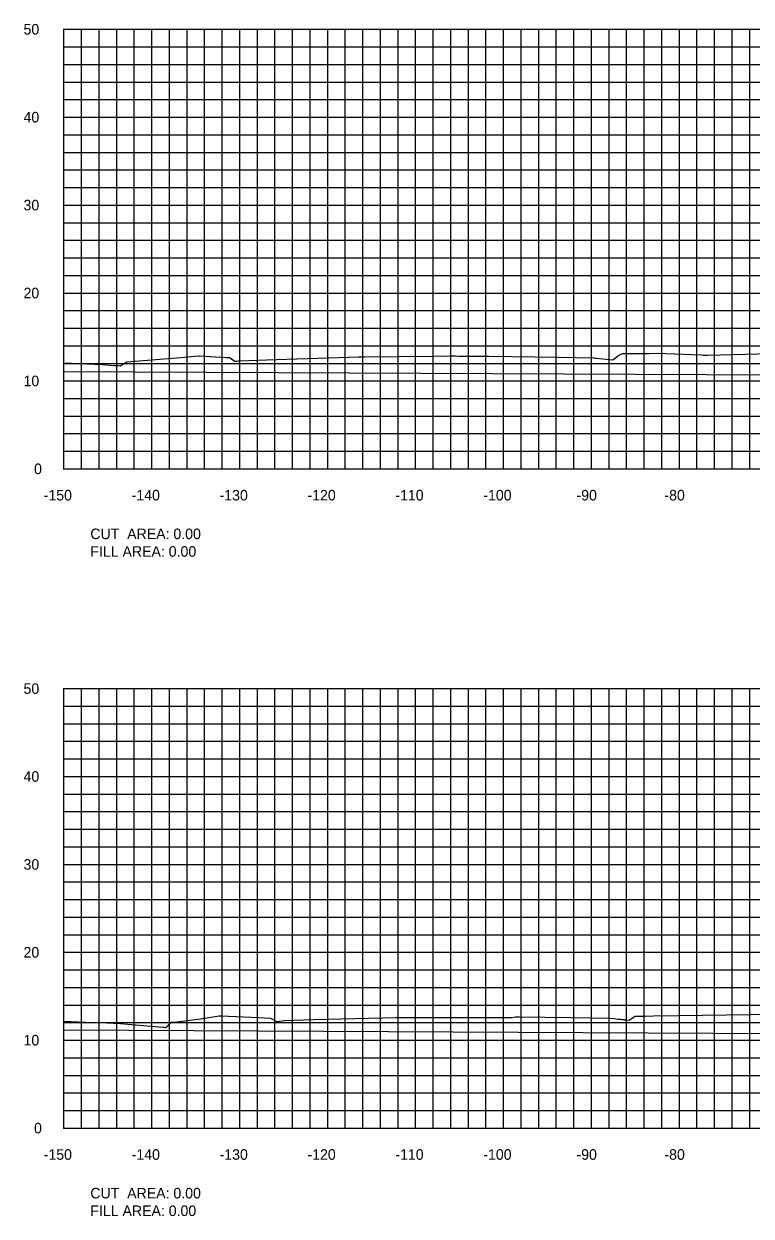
# Model space of a CAD drawing. Extents: x 1800880 to 1814006, y 250083 to 250560.
# Drawn here: x 1810976.4 to 1811059.2, y 250089.4 to 250225 of the extents above; entities that cross this region are included whole.
import ezdxf

# ---------------------------------------------------------------- set-up
doc = ezdxf.new("R2010")
doc.units = 0
for name, color, linetype in [('33', 7, 'Continuous'), ('CL-CNST', 7, 'Continuous'), ('DESIGN - DRAINAGE - Bridges', 7, 'Continuous'), ('DRAINAGETXT', 7, 'Continuous'), ('Level 46', 7, 'Continuous'), ('Level 62', 7, 'Continuous')]:
    doc.layers.add(name, color=color, linetype=linetype)

msp = doc.modelspace()

# ---------------------------------------------------------------- linework, layer by layer
at = {"layer": 'CL-CNST'}
for points in [[(1810981, 250186.49), (1810985.36, 250186.28), (1810986.67, 250186.19), (1810987.22, 250186.17), (1810987.38, 250186.15), (1810988.07, 250186.56), (1810988.13, 250186.6), (1810994.29, 250187.09), (1810996.32, 250187.29), (1810996.41, 250187.29), (1810999.45, 250187.1), (1810999.86, 250187.09), (1810999.89, 250187.07), (1811000.48, 250186.65), (1811000.52, 250186.66), (1811000.53, 250186.66), (1811000.55, 250186.66), (1811000.58, 250186.66), (1811000.67, 250186.67), (1811000.83, 250186.7), (1811001.02, 250186.73), (1811004.03, 250186.82), (1811007.47, 250186.93), (1811011.11, 250187.05), (1811014.5, 250187.16), (1811014.63, 250187.16), (1811015.18, 250187.16), (1811022.99, 250187.25), (1811024.88, 250187.27), (1811025.03, 250187.27), (1811025.55, 250187.27), (1811025.92, 250187.26), (1811026.2, 250187.26), (1811026.42, 250187.26), (1811028.88, 250187.23), (1811029.06, 250187.25), (1811029.08, 250187.25), (1811029.09, 250187.25), (1811029.11, 250187.25), (1811029.14, 250187.25), (1811029.16, 250187.25), (1811029.19, 250187.25), (1811029.21, 250187.25), (1811029.24, 250187.25), (1811029.26, 250187.25), (1811029.29, 250187.25), (1811029.3, 250187.25), (1811029.32, 250187.25), (1811037.17, 250187.12), (1811041.22, 250187.06), (1811041.25, 250187.06), (1811041.36, 250187.04), (1811041.45, 250187.03), (1811041.54, 250187.02), (1811043.42, 250186.84), (1811043.73, 250187.04), (1811044.09, 250187.31), (1811044.29, 250187.45), (1811044.57, 250187.54), (1811047.49, 250187.54), (1811047.57, 250187.54), (1811048.5, 250187.57), (1811053.47, 250187.38), (1811053.69, 250187.37), (1811053.92, 250187.37), (1811054.24, 250187.37), (1811061.29, 250187.56)], [(1810981, 250111.58), (1810984.28, 250111.45), (1810985.82, 250111.4), (1810987.43, 250111.33), (1810988.28, 250111.27), (1810992.23, 250110.92), (1810992.37, 250110.92), (1810992.54, 250110.86), (1810992.89, 250111.13), (1810993.07, 250111.37), (1810993.24, 250111.48), (1810993.26, 250111.48), (1810993.52, 250111.48), (1810996.52, 250111.85), (1810998.66, 250112.22), (1810998.89, 250112.22), (1811003.13, 250112.01), (1811004.49, 250111.95), (1811004.66, 250111.85), (1811005.18, 250111.54), (1811005.52, 250111.6), (1811005.85, 250111.65), (1811006.02, 250111.68), (1811009.37, 250111.77), (1811018.78, 250112.02), (1811021.87, 250112.02), (1811028.54, 250112.02), (1811030.56, 250112.03), (1811030.61, 250112.03), (1811030.65, 250112.02), (1811030.69, 250112.02), (1811030.71, 250112.02), (1811030.74, 250112.02), (1811030.76, 250112.02), (1811030.78, 250112.02), (1811030.79, 250112.02), (1811030.8, 250112.02), (1811030.82, 250112.02), (1811030.83, 250112.02), (1811030.84, 250112.02), (1811030.84, 250112.01), (1811031.87, 250112.03), (1811031.93, 250112.03), (1811032.35, 250112.08), (1811032.71, 250112.08), (1811032.83, 250112.08), (1811038.66, 250112), (1811043.02, 250111.95), (1811043.11, 250111.94), (1811043.54, 250111.9), (1811043.83, 250111.87), (1811044.03, 250111.84), (1811044.19, 250111.83), (1811044.31, 250111.81), (1811044.41, 250111.8), (1811044.48, 250111.79), (1811044.55, 250111.79), (1811044.61, 250111.78), (1811044.66, 250111.77), (1811044.7, 250111.77), (1811044.73, 250111.77), (1811044.77, 250111.76), (1811044.79, 250111.76), (1811044.87, 250111.75), (1811044.9, 250111.75), (1811044.92, 250111.75), (1811044.94, 250111.75), (1811044.96, 250111.75), (1811044.98, 250111.74), (1811045.3, 250111.7), (1811045.88, 250112.13), (1811045.93, 250112.18), (1811045.93, 250112.18), (1811047.08, 250112.18), (1811048.05, 250112.21), (1811064.65, 250112.43)]]:
    msp.add_lwpolyline(points, dxfattribs=at)
at = {"layer": 'DESIGN - DRAINAGE - Bridges'}
for p, q in [((1810980.94, 250224.43), (1810981, 250224.43)), ((1810981, 250174.43), (1810981, 250224.43)), ((1810980.94, 250214.43), (1810981, 250214.43)), ((1810980.94, 250204.43), (1810981, 250204.43)), ((1810980.94, 250194.43), (1810981, 250194.43)), ((1810980.94, 250184.43), (1810981, 250184.43)), ((1810980.94, 250174.43), (1810981, 250174.43)), ((1810981, 250174.43), (1811281, 250174.43)), ((1810981, 250174.37), (1810981, 250174.43)), ((1810991, 250174.37), (1810991, 250174.43)), ((1811001, 250174.37), (1811001, 250174.43)), ((1811011, 250174.37), (1811011, 250174.43)), ((1811021, 250174.37), (1811021, 250174.43)), ((1811031, 250174.37), (1811031, 250174.43)), ((1811041, 250174.37), (1811041, 250174.43)), ((1811051, 250174.37), (1811051, 250174.43)), ((1810980.94, 250149.43), (1810981, 250149.43)), ((1810981, 250099.43), (1810981, 250149.43)), ((1810980.94, 250139.43), (1810981, 250139.43)), ((1810980.94, 250129.43), (1810981, 250129.43)), ((1810980.94, 250119.43), (1810981, 250119.43)), ((1810980.94, 250109.43), (1810981, 250109.43)), ((1810980.94, 250099.43), (1810981, 250099.43)), ((1810981, 250099.43), (1811281, 250099.43)), ((1810981, 250099.37), (1810981, 250099.43)), ((1810991, 250099.37), (1810991, 250099.43)), ((1811001, 250099.37), (1811001, 250099.43)), ((1811011, 250099.37), (1811011, 250099.43)), ((1811021, 250099.37), (1811021, 250099.43)), ((1811031, 250099.37), (1811031, 250099.43)), ((1811041, 250099.37), (1811041, 250099.43)), ((1811051, 250099.37), (1811051, 250099.43))]:
    msp.add_line(p, q, dxfattribs=at)
at = {"layer": 'Level 46'}
for p, q in [((1810981, 250224.43), (1811281, 250224.43)), ((1810981, 250174.43), (1810981, 250224.43)), ((1810983, 250174.43), (1810983, 250224.43)), ((1810985, 250174.43), (1810985, 250224.43)), ((1810987, 250174.43), (1810987, 250224.43)), ((1810989, 250174.43), (1810989, 250224.43)), ((1810991, 250174.43), (1810991, 250224.43)), ((1810993, 250174.43), (1810993, 250224.43)), ((1810995, 250174.43), (1810995, 250224.43)), ((1810997, 250174.43), (1810997, 250224.43)), ((1810999, 250174.43), (1810999, 250224.43)), ((1811001, 250174.43), (1811001, 250224.43)), ((1811003, 250174.43), (1811003, 250224.43)), ((1811005, 250174.43), (1811005, 250224.43)), ((1811007, 250174.43), (1811007, 250224.43)), ((1811009, 250174.43), (1811009, 250224.43)), ((1811011, 250174.43), (1811011, 250224.43)), ((1811013, 250174.43), (1811013, 250224.43)), ((1811015, 250174.43), (1811015, 250224.43)), ((1811017, 250174.43), (1811017, 250224.43)), ((1811019, 250174.43), (1811019, 250224.43)), ((1811021, 250174.43), (1811021, 250224.43)), ((1811023, 250174.43), (1811023, 250224.43)), ((1811025, 250174.43), (1811025, 250224.43)), ((1811027, 250174.43), (1811027, 250224.43)), ((1811029, 250174.43), (1811029, 250224.43)), ((1811031, 250174.43), (1811031, 250224.43)), ((1811033, 250174.43), (1811033, 250224.43)), ((1811035, 250174.43), (1811035, 250224.43)), ((1811037, 250174.43), (1811037, 250224.43)), ((1811039, 250174.43), (1811039, 250224.43)), ((1811041, 250174.43), (1811041, 250224.43)), ((1811043, 250174.43), (1811043, 250224.43)), ((1811045, 250174.43), (1811045, 250224.43)), ((1811047, 250174.43), (1811047, 250224.43)), ((1811049, 250174.43), (1811049, 250224.43)), ((1811051, 250174.43), (1811051, 250224.43)), ((1811053, 250174.43), (1811053, 250224.43)), ((1811055, 250174.43), (1811055, 250224.43)), ((1811057, 250174.43), (1811057, 250224.43)), ((1811059, 250174.43), (1811059, 250224.43)), ((1810981, 250222.43), (1811281, 250222.43)), ((1810981, 250220.43), (1811281, 250220.43)), ((1810981, 250218.43), (1811281, 250218.43)), ((1810981, 250216.43), (1811281, 250216.43)), ((1810981, 250214.43), (1811281, 250214.43)), ((1810981, 250212.43), (1811281, 250212.43)), ((1810981, 250210.43), (1811281, 250210.43)), ((1810981, 250208.43), (1811281, 250208.43)), ((1810981, 250206.43), (1811281, 250206.43)), ((1810981, 250204.43), (1811281, 250204.43)), ((1810981, 250202.43), (1811281, 250202.43)), ((1810981, 250200.43), (1811281, 250200.43)), ((1810981, 250198.43), (1811281, 250198.43)), ((1810981, 250196.43), (1811281, 250196.43)), ((1810981, 250194.43), (1811281, 250194.43)), ((1810981, 250192.43), (1811281, 250192.43)), ((1810981, 250190.43), (1811281, 250190.43)), ((1810981, 250188.43), (1811281, 250188.43)), ((1810981, 250186.43), (1811281, 250186.43)), ((1810981, 250184.43), (1811281, 250184.43)), ((1810981, 250182.43), (1811281, 250182.43)), ((1810981, 250180.43), (1811281, 250180.43)), ((1810981, 250178.43), (1811281, 250178.43)), ((1810981, 250176.43), (1811281, 250176.43)), ((1810981, 250174.43), (1811281, 250174.43)), ((1810981, 250149.43), (1811281, 250149.43)), ((1810981, 250099.43), (1810981, 250149.43)), ((1810983, 250099.43), (1810983, 250149.43)), ((1810985, 250099.43), (1810985, 250149.43)), ((1810987, 250099.43), (1810987, 250149.43)), ((1810989, 250099.43), (1810989, 250149.43)), ((1810991, 250099.43), (1810991, 250149.43)), ((1810993, 250099.43), (1810993, 250149.43)), ((1810995, 250099.43), (1810995, 250149.43)), ((1810997, 250099.43), (1810997, 250149.43)), ((1810999, 250099.43), (1810999, 250149.43)), ((1811001, 250099.43), (1811001, 250149.43)), ((1811003, 250099.43), (1811003, 250149.43)), ((1811005, 250099.43), (1811005, 250149.43)), ((1811007, 250099.43), (1811007, 250149.43)), ((1811009, 250099.43), (1811009, 250149.43)), ((1811011, 250099.43), (1811011, 250149.43)), ((1811013, 250099.43), (1811013, 250149.43)), ((1811015, 250099.43), (1811015, 250149.43)), ((1811017, 250099.43), (1811017, 250149.43)), ((1811019, 250099.43), (1811019, 250149.43)), ((1811021, 250099.43), (1811021, 250149.43)), ((1811023, 250099.43), (1811023, 250149.43)), ((1811025, 250099.43), (1811025, 250149.43)), ((1811027, 250099.43), (1811027, 250149.43)), ((1811029, 250099.43), (1811029, 250149.43)), ((1811031, 250099.43), (1811031, 250149.43)), ((1811033, 250099.43), (1811033, 250149.43)), ((1811035, 250099.43), (1811035, 250149.43)), ((1811037, 250099.43), (1811037, 250149.43)), ((1811039, 250099.43), (1811039, 250149.43)), ((1811041, 250099.43), (1811041, 250149.43)), ((1811043, 250099.43), (1811043, 250149.43)), ((1811045, 250099.43), (1811045, 250149.43)), ((1811047, 250099.43), (1811047, 250149.43)), ((1811049, 250099.43), (1811049, 250149.43)), ((1811051, 250099.43), (1811051, 250149.43)), ((1811053, 250099.43), (1811053, 250149.43)), ((1811055, 250099.43), (1811055, 250149.43)), ((1811057, 250099.43), (1811057, 250149.43)), ((1811059, 250099.43), (1811059, 250149.43)), ((1810981, 250147.43), (1811281, 250147.43)), ((1810981, 250145.43), (1811281, 250145.43)), ((1810981, 250143.43), (1811281, 250143.43)), ((1810981, 250141.43), (1811281, 250141.43)), ((1810981, 250139.43), (1811281, 250139.43)), ((1810981, 250137.43), (1811281, 250137.43)), ((1810981, 250135.43), (1811281, 250135.43)), ((1810981, 250133.43), (1811281, 250133.43)), ((1810981, 250131.43), (1811281, 250131.43)), ((1810981, 250129.43), (1811281, 250129.43)), ((1810981, 250127.43), (1811281, 250127.43)), ((1810981, 250125.43), (1811281, 250125.43)), ((1810981, 250123.43), (1811281, 250123.43)), ((1810981, 250121.43), (1811281, 250121.43)), ((1810981, 250119.43), (1811281, 250119.43)), ((1810981, 250117.43), (1811281, 250117.43)), ((1810981, 250115.43), (1811281, 250115.43)), ((1810981, 250113.43), (1811281, 250113.43)), ((1810981, 250111.43), (1811281, 250111.43)), ((1810981, 250109.43), (1811281, 250109.43)), ((1810981, 250107.43), (1811281, 250107.43)), ((1810981, 250105.43), (1811281, 250105.43)), ((1810981, 250103.43), (1811281, 250103.43)), ((1810981, 250101.43), (1811281, 250101.43)), ((1810981, 250099.43), (1811281, 250099.43))]:
    msp.add_line(p, q, dxfattribs=at)
at = {"layer": 'Level 62'}
for p, q in [((1810981, 250185.52), (1811281, 250184.02)), ((1810981, 250110.6), (1811281, 250109.1))]:
    msp.add_line(p, q, dxfattribs=at)

# ---------------------------------------------------------------- texts
for s, p in [('-150', (1810978.7, 250170.83)), ('-140', (1810988.7, 250170.83)), ('-130', (1810998.7, 250170.83)), ('-120', (1811008.7, 250170.83)), ('-110', (1811018.7, 250170.83)), ('-100', (1811028.7, 250170.83)), ('-90', (1811039.3, 250170.83)), ('-80', (1811049.3, 250170.83)), ('-150', (1810978.7, 250095.83)), ('-140', (1810988.7, 250095.83)), ('-130', (1810998.7, 250095.83)), ('-120', (1811008.7, 250095.83)), ('-110', (1811018.7, 250095.83)), ('-100', (1811028.7, 250095.83)), ('-90', (1811039.3, 250095.83)), ('-80', (1811049.3, 250095.83))]:
    msp.add_text(s, height=1.2).set_placement(p)
at = {"layer": '33'}
for s, p in [('50', (1810976.4, 250223.83)), ('40', (1810976.4, 250213.83)), ('30', (1810976.4, 250203.83)), ('20', (1810976.4, 250193.83)), ('10', (1810976.4, 250183.83)), ('0', (1810977.6, 250173.83)), ('50', (1810976.4, 250148.83)), ('40', (1810976.4, 250138.83)), ('30', (1810976.4, 250128.83)), ('20', (1810976.4, 250118.83)), ('10', (1810976.4, 250108.83)), ('0', (1810977.6, 250098.83))]:
    msp.add_text(s, height=1.2, dxfattribs=at).set_placement(p)
at = {"layer": 'DESIGN - DRAINAGE - Bridges'}
for p in [(1810981, 250174.43), (1810981, 250099.43)]:
    msp.add_text('-', height=0.0001, dxfattribs=at).set_placement(p)
at = {"layer": 'DRAINAGETXT'}
for s, p in [('CUT  AREA: 0.00', (1810984, 250166.43)), ('FILL AREA: 0.00', (1810984, 250164.43)), ('CUT  AREA: 0.00', (1810984, 250091.43)), ('FILL AREA: 0.00', (1810984, 250089.43))]:
    msp.add_text(s, height=1.2, dxfattribs=at).set_placement(p)

doc.saveas('drawing.dxf')
